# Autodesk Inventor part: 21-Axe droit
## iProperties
Created: 2011-02
Part Number: 21-Axe droit
Document SubType Name: Modeling
Designer: eric
Density: 1 g/cm^3
Author: eric
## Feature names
1. Base1
